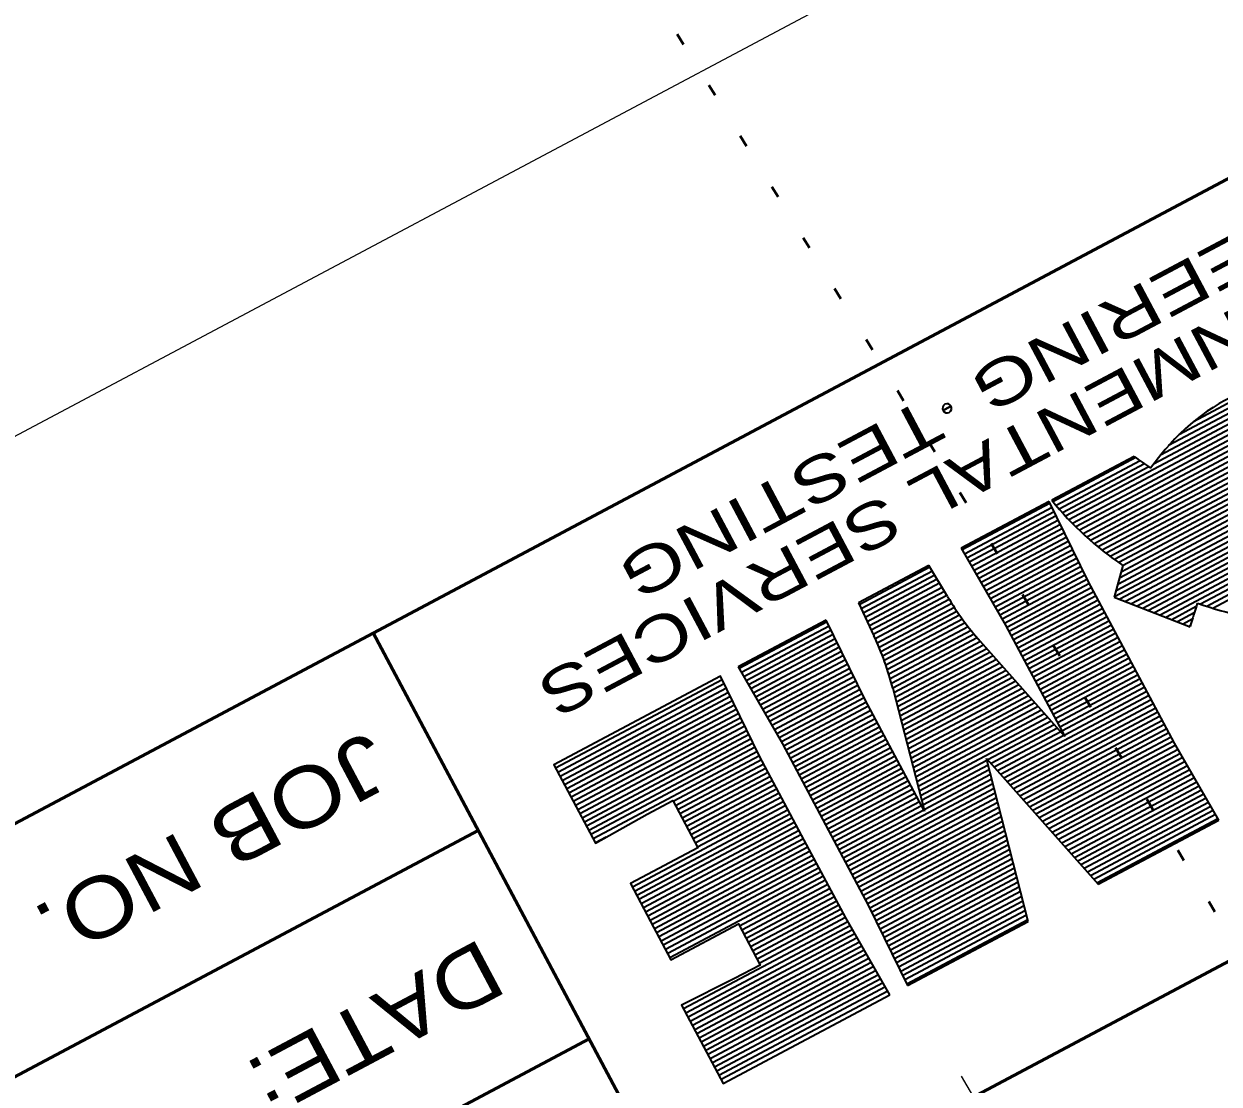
# Model space of a CAD drawing. Extents: x 2402199 to 2404507, y 568050 to 571478.
# Drawn here: x 2402340.7 to 2402382.64, y 571177.1 to 571214.31 of the extents above; entities that cross this region are included whole.
import ezdxf

# ---------------------------------------------------------------- set-up
doc = ezdxf.new("R2010")
doc.units = 0
doc.header["$LTSCALE"] = 1.4
doc.linetypes.add('DOTTED', pattern=[1.5, 0.3, -1.2])
for name, color, linetype, lineweight in [('15', 7, 'DOTTED', 40), ('6', 7, 'Continuous', 35), ('63', 7, 'Continuous', 35)]:
    doc.layers.add(name, color=color, linetype=linetype, lineweight=lineweight)

msp = doc.modelspace()

# ---------------------------------------------------------------- linework, layer by layer
at = {"layer": '15'}
msp.add_arc((2399911.332, 569690.208), 2887.133, 22.84472, 37.57762, dxfattribs=at)
at = {"layer": '6', "lineweight": 13}
msp.add_line((2402373.595, 571177.375), (2402414.387, 571107.848), dxfattribs=at)
at = {"layer": '63', "lineweight": 13}
msp.add_line((2402247.375, 571150.383), (2402538.748, 571305.309), dxfattribs=at)
at = {"layer": '63'}
for p, q in [((2402531.138, 571287.671), (2402266.253, 571146.83)), ((2402385.891, 571201.617), (2402377.257, 571197.026)), ((2402386.106, 571201.544), (2402377.374, 571196.902)), ((2402386.302, 571201.462), (2402377.494, 571196.779)), ((2402385.655, 571201.679), (2402380.343, 571198.854)), ((2402385.393, 571201.726), (2402380.591, 571199.172)), ((2402385.092, 571201.753), (2402380.871, 571199.508)), ((2402384.732, 571201.748), (2402381.229, 571199.886)), ((2402384.25, 571201.679), (2402381.74, 571200.344)), ((2402386.484, 571201.372), (2402377.616, 571196.656)), ((2402386.653, 571201.275), (2402377.74, 571196.535)), ((2402386.811, 571201.172), (2402377.867, 571196.416)), ((2402386.958, 571201.063), (2402377.996, 571196.298)), ((2402372.955, 571200.741), (2402373.096, 571200.816)), ((2402373.096, 571200.816), (2402372.955, 571200.741)), ((2402373.096, 571200.816), (2402373.238, 571200.892)), ((2402373.238, 571200.892), (2402373.096, 571200.816)), ((2402387.095, 571200.949), (2402378.127, 571196.181)), ((2402387.223, 571200.83), (2402378.261, 571196.065)), ((2402387.342, 571200.707), (2402378.398, 571195.951)), ((2402387.454, 571200.579), (2402378.537, 571195.838)), ((2402387.557, 571200.447), (2402378.679, 571195.727)), ((2402387.653, 571200.311), (2402378.824, 571195.617)), ((2402379.661, 571199.13), (2402376.767, 571197.591)), ((2402379.723, 571199.085), (2402376.811, 571197.537)), ((2402379.871, 571198.977), (2402376.919, 571197.407)), ((2402380.596, 571199.179), (2402380.237, 571198.718)), ((2402380.021, 571198.87), (2402377.03, 571197.279)), ((2402380.172, 571198.763), (2402377.143, 571197.152)), ((2402383.644, 571197.993), (2402378.971, 571195.508)), ((2402388.326, 571197.866), (2402380.371, 571193.637)), ((2402388.326, 571197.679), (2402380.573, 571193.557)), ((2402376.682, 571197.546), (2402373.595, 571195.905)), ((2402376.712, 571197.484), (2402373.629, 571195.845)), ((2402376.785, 571197.336), (2402373.712, 571195.702)), ((2402378.053, 571194.748), (2402376.682, 571197.546)), ((2402383.284, 571197.615), (2402379.121, 571195.401)), ((2402383.174, 571197.369), (2402379.258, 571195.287)), ((2402388.319, 571197.489), (2402380.775, 571193.478)), ((2402388.305, 571197.294), (2402381.992, 571193.938)), ((2402376.857, 571197.188), (2402373.794, 571195.559)), ((2402376.93, 571197.039), (2402373.876, 571195.416)), ((2402377.003, 571196.891), (2402373.959, 571195.272)), ((2402383.534, 571196.813), (2402379.025, 571194.416)), ((2402383.349, 571196.902), (2402379.084, 571194.634)), ((2402383.166, 571196.991), (2402379.142, 571194.851)), ((2402383.066, 571197.125), (2402379.2, 571195.069)), ((2402388.284, 571197.096), (2402382.207, 571193.865)), ((2402388.254, 571196.894), (2402382.428, 571193.796)), ((2402377.075, 571196.743), (2402374.041, 571195.129)), ((2402377.148, 571196.595), (2402374.123, 571194.986)), ((2402377.22, 571196.446), (2402374.206, 571194.843)), ((2402383.721, 571196.726), (2402378.967, 571194.198)), ((2402383.91, 571196.639), (2402379.159, 571194.113)), ((2402384.101, 571196.554), (2402379.361, 571194.034)), ((2402384.294, 571196.47), (2402379.563, 571193.954)), ((2402384.489, 571196.387), (2402379.765, 571193.875)), ((2402377.293, 571196.298), (2402374.288, 571194.7)), ((2402377.366, 571196.15), (2402374.37, 571194.557)), ((2402377.438, 571196.001), (2402374.453, 571194.414)), ((2402384.686, 571196.304), (2402379.967, 571193.796)), ((2402384.886, 571196.224), (2402380.169, 571193.716)), ((2402373.595, 571195.905), (2402375.149, 571193.204)), ((2402377.511, 571195.853), (2402374.535, 571194.271)), ((2402377.584, 571195.705), (2402374.617, 571194.128)), ((2402377.656, 571195.557), (2402374.7, 571193.985)), ((2402372.461, 571195.302), (2402369.987, 571193.986)), ((2402372.496, 571195.242), (2402370.016, 571193.924)), ((2402373.112, 571194.209), (2402372.461, 571195.302)), ((2402377.729, 571195.408), (2402374.782, 571193.841)), ((2402377.801, 571195.26), (2402374.864, 571193.698)), ((2402379.263, 571195.304), (2402378.965, 571194.189)), ((2402372.581, 571195.1), (2402370.086, 571193.774)), ((2402372.665, 571194.959), (2402370.157, 571193.625)), ((2402372.75, 571194.816), (2402370.227, 571193.475)), ((2402377.874, 571195.112), (2402374.947, 571193.555)), ((2402377.947, 571194.964), (2402375.029, 571193.412)), ((2402378.019, 571194.815), (2402375.111, 571193.269)), ((2402381.074, 571189.065), (2402378.053, 571194.748)), ((2402372.834, 571194.674), (2402370.297, 571193.326)), ((2402372.919, 571194.533), (2402370.368, 571193.176)), ((2402373.004, 571194.391), (2402370.438, 571193.027)), ((2402378.095, 571194.668), (2402375.191, 571193.125)), ((2402378.172, 571194.523), (2402375.268, 571192.979)), ((2402378.249, 571194.377), (2402375.346, 571192.833)), ((2402369.987, 571193.986), (2402370.528, 571192.835)), ((2402373.088, 571194.249), (2402370.508, 571192.877)), ((2402373.173, 571194.107), (2402370.578, 571192.728)), ((2402373.261, 571193.967), (2402370.646, 571192.576)), ((2402378.327, 571194.231), (2402375.423, 571192.687)), ((2402378.404, 571194.086), (2402375.501, 571192.542)), ((2402378.482, 571193.94), (2402375.578, 571192.396)), ((2402378.965, 571194.189), (2402381.623, 571193.144)), ((2402373.351, 571193.828), (2402370.711, 571192.424)), ((2402373.443, 571193.69), (2402370.774, 571192.271)), ((2402373.537, 571193.553), (2402370.834, 571192.116)), ((2402378.559, 571193.794), (2402375.655, 571192.25)), ((2402378.637, 571193.649), (2402375.733, 571192.105)), ((2402378.714, 571193.503), (2402375.811, 571191.959)), ((2402381.84, 571193.856), (2402380.978, 571193.398)), ((2402381.77, 571193.633), (2402381.18, 571193.319)), ((2402368.852, 571193.383), (2402365.765, 571191.742)), ((2402368.883, 571193.321), (2402365.8, 571191.682)), ((2402368.955, 571193.173), (2402365.882, 571191.539)), ((2402369.028, 571193.025), (2402365.964, 571191.395)), ((2402370.223, 571190.584), (2402368.852, 571193.383)), ((2402373.634, 571193.418), (2402370.892, 571191.96)), ((2402373.733, 571193.284), (2402370.948, 571191.803)), ((2402373.835, 571193.151), (2402371.001, 571191.644)), ((2402373.939, 571193.02), (2402371.052, 571191.485)), ((2402375.149, 571193.204), (2402377.225, 571189.299)), ((2402378.791, 571193.357), (2402375.888, 571191.813)), ((2402378.869, 571193.211), (2402375.965, 571191.667)), ((2402378.947, 571193.066), (2402376.043, 571191.522)), ((2402381.702, 571193.41), (2402381.382, 571193.239)), ((2402381.636, 571193.188), (2402381.584, 571193.16)), ((2402369.101, 571192.876), (2402366.047, 571191.253)), ((2402369.173, 571192.728), (2402366.129, 571191.109)), ((2402374.045, 571192.889), (2402371.101, 571191.323)), ((2402374.154, 571192.76), (2402371.146, 571191.161)), ((2402374.266, 571192.633), (2402371.19, 571190.997)), ((2402377.225, 571189.299), (2402374.265, 571192.633)), ((2402379.024, 571192.92), (2402376.12, 571191.376)), ((2402379.101, 571192.775), (2402376.198, 571191.231)), ((2402379.179, 571192.629), (2402376.275, 571191.085)), ((2402369.246, 571192.58), (2402366.211, 571190.966)), ((2402369.318, 571192.431), (2402366.294, 571190.823)), ((2402369.391, 571192.283), (2402366.376, 571190.68)), ((2402374.379, 571192.506), (2402371.232, 571190.833)), ((2402374.491, 571192.379), (2402371.274, 571190.668)), ((2402374.604, 571192.252), (2402371.317, 571190.504)), ((2402379.257, 571192.483), (2402376.353, 571190.939)), ((2402379.334, 571192.337), (2402376.43, 571190.794)), ((2402379.411, 571192.192), (2402376.507, 571190.648)), ((2402369.464, 571192.135), (2402366.458, 571190.537)), ((2402369.536, 571191.986), (2402366.541, 571190.394)), ((2402369.609, 571191.838), (2402366.623, 571190.251)), ((2402374.717, 571192.125), (2402371.359, 571190.34)), ((2402374.829, 571191.998), (2402371.401, 571190.175)), ((2402374.942, 571191.871), (2402371.443, 571190.01)), ((2402379.489, 571192.046), (2402376.585, 571190.502)), ((2402379.566, 571191.9), (2402376.663, 571190.356)), ((2402365.765, 571191.742), (2402367.319, 571189.041)), ((2402369.681, 571191.69), (2402366.705, 571190.108)), ((2402369.754, 571191.542), (2402366.788, 571189.965)), ((2402369.826, 571191.394), (2402366.87, 571189.821)), ((2402375.055, 571191.744), (2402371.485, 571189.846)), ((2402375.167, 571191.617), (2402371.528, 571189.682)), ((2402375.28, 571191.49), (2402371.57, 571189.517)), ((2402375.393, 571191.363), (2402371.612, 571189.353)), ((2402379.644, 571191.755), (2402376.74, 571190.211)), ((2402379.721, 571191.609), (2402376.817, 571190.065)), ((2402379.799, 571191.463), (2402376.895, 571189.919)), ((2402365.205, 571191.292), (2402359.36, 571188.184)), ((2402365.277, 571191.144), (2402359.437, 571188.038)), ((2402365.35, 571190.995), (2402359.514, 571187.893)), ((2402369.899, 571191.245), (2402366.952, 571189.678)), ((2402369.972, 571191.097), (2402367.035, 571189.535)), ((2402370.044, 571190.949), (2402367.117, 571189.392)), ((2402371.19, 571190.998), (2402372.299, 571186.681)), ((2402375.505, 571191.236), (2402371.655, 571189.189)), ((2402375.618, 571191.109), (2402371.697, 571189.024)), ((2402375.731, 571190.982), (2402371.739, 571188.86)), ((2402379.876, 571191.318), (2402376.973, 571189.774)), ((2402379.953, 571191.172), (2402377.05, 571189.628)), ((2402380.031, 571191.026), (2402377.127, 571189.482)), ((2402365.422, 571190.847), (2402359.592, 571187.747)), ((2402365.495, 571190.699), (2402359.669, 571187.601)), ((2402365.568, 571190.551), (2402359.747, 571187.456)), ((2402370.117, 571190.801), (2402367.199, 571189.249)), ((2402370.19, 571190.652), (2402367.282, 571189.106)), ((2402370.265, 571190.505), (2402367.361, 571188.961)), ((2402372.299, 571186.681), (2402370.223, 571190.584)), ((2402375.843, 571190.855), (2402371.781, 571188.695)), ((2402375.956, 571190.728), (2402371.823, 571188.531)), ((2402376.069, 571190.601), (2402371.865, 571188.367)), ((2402380.186, 571190.735), (2402374.976, 571187.965)), ((2402380.263, 571190.589), (2402375.089, 571187.838)), ((2402380.109, 571190.88), (2402377.205, 571189.336)), ((2402365.64, 571190.402), (2402359.824, 571187.31)), ((2402365.713, 571190.254), (2402359.902, 571187.164)), ((2402365.786, 571190.106), (2402359.979, 571187.019)), ((2402370.342, 571190.36), (2402367.439, 571188.816)), ((2402370.42, 571190.214), (2402367.516, 571188.67)), ((2402376.181, 571190.475), (2402371.908, 571188.202)), ((2402376.294, 571190.348), (2402371.95, 571188.037)), ((2402376.407, 571190.221), (2402371.992, 571187.873)), ((2402376.52, 571190.093), (2402372.035, 571187.709)), ((2402380.341, 571190.444), (2402375.201, 571187.711)), ((2402380.418, 571190.298), (2402375.314, 571187.584)), ((2402380.496, 571190.152), (2402375.427, 571187.457)), ((2402365.858, 571189.958), (2402360.056, 571186.873)), ((2402365.931, 571189.809), (2402360.134, 571186.727)), ((2402370.497, 571190.068), (2402367.593, 571188.524)), ((2402370.575, 571189.922), (2402367.671, 571188.378)), ((2402370.652, 571189.777), (2402367.749, 571188.233)), ((2402376.632, 571189.966), (2402372.077, 571187.544)), ((2402376.745, 571189.84), (2402372.119, 571187.38)), ((2402376.858, 571189.713), (2402374.525, 571188.473)), ((2402380.573, 571190.006), (2402375.54, 571187.33)), ((2402380.651, 571189.861), (2402375.652, 571187.203)), ((2402380.728, 571189.715), (2402375.765, 571187.076)), ((2402366.004, 571189.661), (2402360.212, 571186.581)), ((2402366.076, 571189.513), (2402360.289, 571186.436)), ((2402366.149, 571189.365), (2402360.367, 571186.29)), ((2402370.73, 571189.631), (2402367.826, 571188.087)), ((2402370.807, 571189.485), (2402367.904, 571187.941)), ((2402370.885, 571189.34), (2402367.981, 571187.796)), ((2402376.97, 571189.586), (2402374.638, 571188.346)), ((2402377.083, 571189.459), (2402374.751, 571188.219)), ((2402377.196, 571189.332), (2402374.863, 571188.092)), ((2402380.806, 571189.569), (2402375.878, 571186.949)), ((2402380.883, 571189.424), (2402375.99, 571186.822)), ((2402380.961, 571189.278), (2402376.103, 571186.695)), ((2402366.221, 571189.216), (2402360.444, 571186.145)), ((2402366.294, 571189.068), (2402360.521, 571185.999)), ((2402366.367, 571188.92), (2402360.599, 571185.853)), ((2402367.319, 571189.041), (2402370.341, 571183.358)), ((2402370.962, 571189.194), (2402368.058, 571187.65)), ((2402371.039, 571189.049), (2402368.136, 571187.505)), ((2402371.117, 571188.903), (2402368.213, 571187.359)), ((2402381.038, 571189.132), (2402376.216, 571186.568)), ((2402381.118, 571188.988), (2402376.328, 571186.441)), ((2402381.2, 571188.845), (2402376.441, 571186.314)), ((2402382.628, 571186.363), (2402381.074, 571189.065)), ((2402366.439, 571188.772), (2402360.676, 571185.708)), ((2402366.512, 571188.623), (2402363.487, 571187.015)), ((2402366.589, 571188.478), (2402363.564, 571186.869)), ((2402371.195, 571188.757), (2402368.291, 571187.213)), ((2402371.272, 571188.611), (2402368.368, 571187.068)), ((2402371.349, 571188.466), (2402368.446, 571186.922)), ((2402374.493, 571188.456), (2402372.161, 571187.216)), ((2402374.474, 571188.53), (2402378.395, 571184.113)), ((2402375.944, 571182.809), (2402374.474, 571188.53)), ((2402381.283, 571188.702), (2402376.554, 571186.188)), ((2402381.365, 571188.559), (2402376.667, 571186.061)), ((2402381.447, 571188.416), (2402376.779, 571185.934)), ((2402366.666, 571188.332), (2402363.641, 571186.723)), ((2402366.744, 571188.186), (2402363.719, 571186.578)), ((2402366.821, 571188.04), (2402363.796, 571186.432)), ((2402371.427, 571188.32), (2402368.523, 571186.776)), ((2402371.504, 571188.174), (2402368.601, 571186.63)), ((2402371.582, 571188.029), (2402368.678, 571186.485)), ((2402374.536, 571188.291), (2402372.203, 571187.051)), ((2402374.578, 571188.127), (2402372.246, 571186.887)), ((2402381.53, 571188.272), (2402376.892, 571185.807)), ((2402381.612, 571188.129), (2402377.005, 571185.679)), ((2402381.694, 571187.986), (2402377.118, 571185.553)), ((2402366.899, 571187.895), (2402363.874, 571186.286)), ((2402366.976, 571187.749), (2402363.951, 571186.14)), ((2402367.053, 571187.603), (2402364.029, 571185.995)), ((2402371.659, 571187.883), (2402368.755, 571186.339)), ((2402371.737, 571187.737), (2402368.833, 571186.193)), ((2402371.814, 571187.591), (2402368.911, 571186.048)), ((2402374.663, 571187.798), (2402369.453, 571185.028)), ((2402374.704, 571187.633), (2402369.53, 571184.882)), ((2402374.62, 571187.962), (2402372.288, 571186.722)), ((2402381.777, 571187.843), (2402377.23, 571185.426)), ((2402381.859, 571187.7), (2402377.343, 571185.299)), ((2402367.131, 571187.458), (2402364.106, 571185.849)), ((2402367.209, 571187.312), (2402364.184, 571185.704)), ((2402367.286, 571187.166), (2402364.261, 571185.558)), ((2402371.891, 571187.446), (2402368.988, 571185.902)), ((2402371.969, 571187.3), (2402369.065, 571185.756)), ((2402372.047, 571187.155), (2402369.143, 571185.61)), ((2402374.747, 571187.469), (2402369.607, 571184.736)), ((2402374.789, 571187.305), (2402369.685, 571184.591)), ((2402381.941, 571187.557), (2402377.456, 571185.172)), ((2402382.024, 571187.414), (2402377.568, 571185.045)), ((2402382.106, 571187.271), (2402377.681, 571184.918)), ((2402367.441, 571186.875), (2402362.051, 571184.009)), ((2402367.518, 571186.729), (2402362.129, 571183.863)), ((2402367.363, 571187.02), (2402364.339, 571185.412)), ((2402372.124, 571187.009), (2402369.22, 571185.465)), ((2402372.201, 571186.863), (2402369.298, 571185.319)), ((2402374.831, 571187.14), (2402369.763, 571184.445)), ((2402374.874, 571186.976), (2402369.84, 571184.299)), ((2402374.916, 571186.811), (2402369.917, 571184.154)), ((2402382.188, 571187.128), (2402377.794, 571184.791)), ((2402382.271, 571186.985), (2402377.906, 571184.664)), ((2402382.353, 571186.841), (2402378.019, 571184.537)), ((2402367.596, 571186.584), (2402362.206, 571183.718)), ((2402367.673, 571186.438), (2402362.283, 571183.572)), ((2402372.279, 571186.718), (2402369.375, 571185.174)), ((2402374.958, 571186.647), (2402369.995, 571184.008)), ((2402375, 571186.483), (2402370.072, 571183.862)), ((2402375.042, 571186.318), (2402370.15, 571183.717)), ((2402382.435, 571186.698), (2402378.132, 571184.41)), ((2402382.518, 571186.555), (2402378.244, 571184.283)), ((2402382.6, 571186.412), (2402378.357, 571184.156)), ((2402378.395, 571184.113), (2402382.628, 571186.363)), ((2402367.751, 571186.292), (2402362.361, 571183.426)), ((2402367.828, 571186.147), (2402362.438, 571183.28)), ((2402367.906, 571186.001), (2402362.516, 571183.135)), ((2402375.085, 571186.154), (2402370.227, 571183.571)), ((2402375.127, 571185.989), (2402370.305, 571183.425)), ((2402361.132, 571185.763), (2402360.754, 571185.562)), ((2402367.983, 571185.855), (2402362.593, 571182.989)), ((2402368.061, 571185.709), (2402362.671, 571182.843)), ((2402368.138, 571185.564), (2402362.748, 571182.698)), ((2402375.169, 571185.825), (2402370.38, 571183.278)), ((2402375.212, 571185.66), (2402370.452, 571183.13)), ((2402375.254, 571185.496), (2402370.525, 571182.982)), ((2402368.215, 571185.418), (2402362.826, 571182.552)), ((2402368.293, 571185.272), (2402362.903, 571182.407)), ((2402368.371, 571185.127), (2402362.981, 571182.261)), ((2402375.296, 571185.331), (2402370.598, 571182.834)), ((2402375.338, 571185.167), (2402370.67, 571182.685)), ((2402368.448, 571184.981), (2402363.058, 571182.115)), ((2402368.525, 571184.835), (2402363.135, 571181.97)), ((2402368.603, 571184.689), (2402363.213, 571181.824)), ((2402375.38, 571185.003), (2402370.743, 571182.537)), ((2402375.422, 571184.838), (2402370.815, 571182.389)), ((2402375.465, 571184.674), (2402370.888, 571182.24)), ((2402368.68, 571184.544), (2402363.291, 571181.678)), ((2402368.758, 571184.398), (2402363.368, 571181.532)), ((2402368.835, 571184.253), (2402365.811, 571182.644)), ((2402375.507, 571184.51), (2402370.961, 571182.092)), ((2402375.549, 571184.345), (2402371.033, 571181.944)), ((2402368.913, 571184.107), (2402365.888, 571182.498)), ((2402368.99, 571183.961), (2402365.965, 571182.353)), ((2402369.067, 571183.816), (2402366.043, 571182.207)), ((2402375.592, 571184.181), (2402371.106, 571181.796)), ((2402375.634, 571184.016), (2402371.178, 571181.647)), ((2402375.676, 571183.852), (2402371.251, 571181.499)), ((2402369.145, 571183.67), (2402366.12, 571182.062)), ((2402369.223, 571183.524), (2402366.198, 571181.916)), ((2402369.3, 571183.378), (2402366.275, 571181.77)), ((2402375.718, 571183.688), (2402371.323, 571181.351)), ((2402375.76, 571183.523), (2402371.396, 571181.203)), ((2402369.377, 571183.233), (2402366.353, 571181.624)), ((2402369.455, 571183.087), (2402366.43, 571181.479)), ((2402370.341, 571183.358), (2402371.711, 571180.559)), ((2402375.803, 571183.358), (2402371.469, 571181.054)), ((2402375.845, 571183.194), (2402371.541, 571180.906)), ((2402375.887, 571183.03), (2402371.614, 571180.758)), ((2402369.614, 571182.798), (2402363.852, 571179.734)), ((2402369.697, 571182.655), (2402363.93, 571179.589)), ((2402369.533, 571182.941), (2402366.507, 571181.333)), ((2402375.929, 571182.865), (2402371.686, 571180.61)), ((2402371.711, 571180.559), (2402375.944, 571182.809)), ((2402369.779, 571182.512), (2402364.007, 571179.443)), ((2402369.861, 571182.369), (2402364.085, 571179.297)), ((2402369.944, 571182.226), (2402364.162, 571179.152)), ((2402370.026, 571182.083), (2402364.24, 571179.006)), ((2402370.108, 571181.939), (2402364.317, 571178.86)), ((2402370.191, 571181.796), (2402364.394, 571178.715)), ((2402370.273, 571181.653), (2402364.472, 571178.569)), ((2402370.355, 571181.51), (2402364.55, 571178.423)), ((2402370.438, 571181.367), (2402364.627, 571178.277)), ((2402370.52, 571181.224), (2402364.704, 571178.132)), ((2402370.602, 571181.081), (2402364.782, 571177.986)), ((2402370.684, 571180.938), (2402364.859, 571177.84)), ((2402370.767, 571180.794), (2402364.937, 571177.695)), ((2402370.849, 571180.652), (2402365.014, 571177.549)), ((2402370.931, 571180.508), (2402365.092, 571177.403)), ((2402371.014, 571180.365), (2402365.169, 571177.258))]:
    msp.add_line(p, q, dxfattribs=at)
at = {"layer": '63', "lineweight": 60}
for p, q in [((2402352.956, 571192.931), (2402364.345, 571171.511)), ((2402356.639, 571186.003), (2402269.936, 571139.902)), ((2402360.531, 571178.684), (2402273.828, 571132.583))]:
    msp.add_line(p, q, dxfattribs=at)
msp.add_lwpolyline([(2402542.527, 571266.252), (2402277.643, 571125.41), (2402266.253, 571146.83), (2402531.138, 571287.671)], close=True, dxfattribs=at)
at = {"layer": '63'}
msp.add_lwpolyline([(2402371.092, 571180.23), (2402369.538, 571182.931), (2402368.084, 571185.665), (2402366.516, 571188.613), (2402365.146, 571191.412), (2402359.297, 571188.302), (2402360.759, 571185.552), (2402362.567, 571186.573), (2402363.467, 571187.051), (2402364.348, 571185.395), (2402361.983, 571184.137), (2402362.694, 571182.799), (2402363.406, 571181.461), (2402365.771, 571182.719), (2402366.538, 571181.277), (2402365.638, 571180.799), (2402363.78, 571179.87), (2402365.243, 571177.12)], close=True, dxfattribs=at)
for centre, radius, start, end in [((2402386.522, 571194.505), 7.547, 111.4011, 141.7347), ((2402373.096, 571200.816), 0.161, 28, 208), ((2402373.096, 571200.816), 0.161, 208, 28), ((2402373.096, 571200.816), 0.0002, 28, 208), ((2402373.096, 571200.816), 0.0002, 208, 28), ((2402393.558, 571217.964), 23.406, 233.5784, 235.3123), ((2402385.794, 571204.937), 11.638, 219.1385, 235.8654), ((2402382.029, 571199.525), 10.381, 210.8042, 221.595), ((2402413.379, 571183.889), 33.077, 162.2417, 163.7511), ((2402385.794, 571204.937), 11.638, 250.3401, 258.6293), ((2402361.135, 571188.415), 10.381, 14.405, 25.1958)]:
    msp.add_arc(centre, radius, start, end, dxfattribs=at)

# ---------------------------------------------------------------- texts
for s, height, width, p in [('ENGINEERING  TESTING', 1.584, 1.35, (2402391.445, 571211.372)), ('ENVIRONMENTAL SERVICES', 1.584, 1.3, (2402392.53, 571209.331)), ('JOB NO.', 2.1, 1.2, (2402352.785, 571189.52)), ('DATE:', 2.1, 1.15, (2402356.748, 571182.238))]:
    msp.add_text(s, height=height, rotation=208, dxfattribs=dict(at, width=width)).set_placement(p)

doc.saveas('drawing.dxf')
